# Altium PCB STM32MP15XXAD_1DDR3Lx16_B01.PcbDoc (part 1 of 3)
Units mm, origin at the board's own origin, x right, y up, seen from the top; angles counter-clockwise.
Board outline 86 x 120 mm, 4 copper layers (Top Layer, Signal Layer 1, Signal Layer 2, Bottom Layer), stack 1.571 mm thick; 118 components, 119 nets, 781 pads, 336 vias.
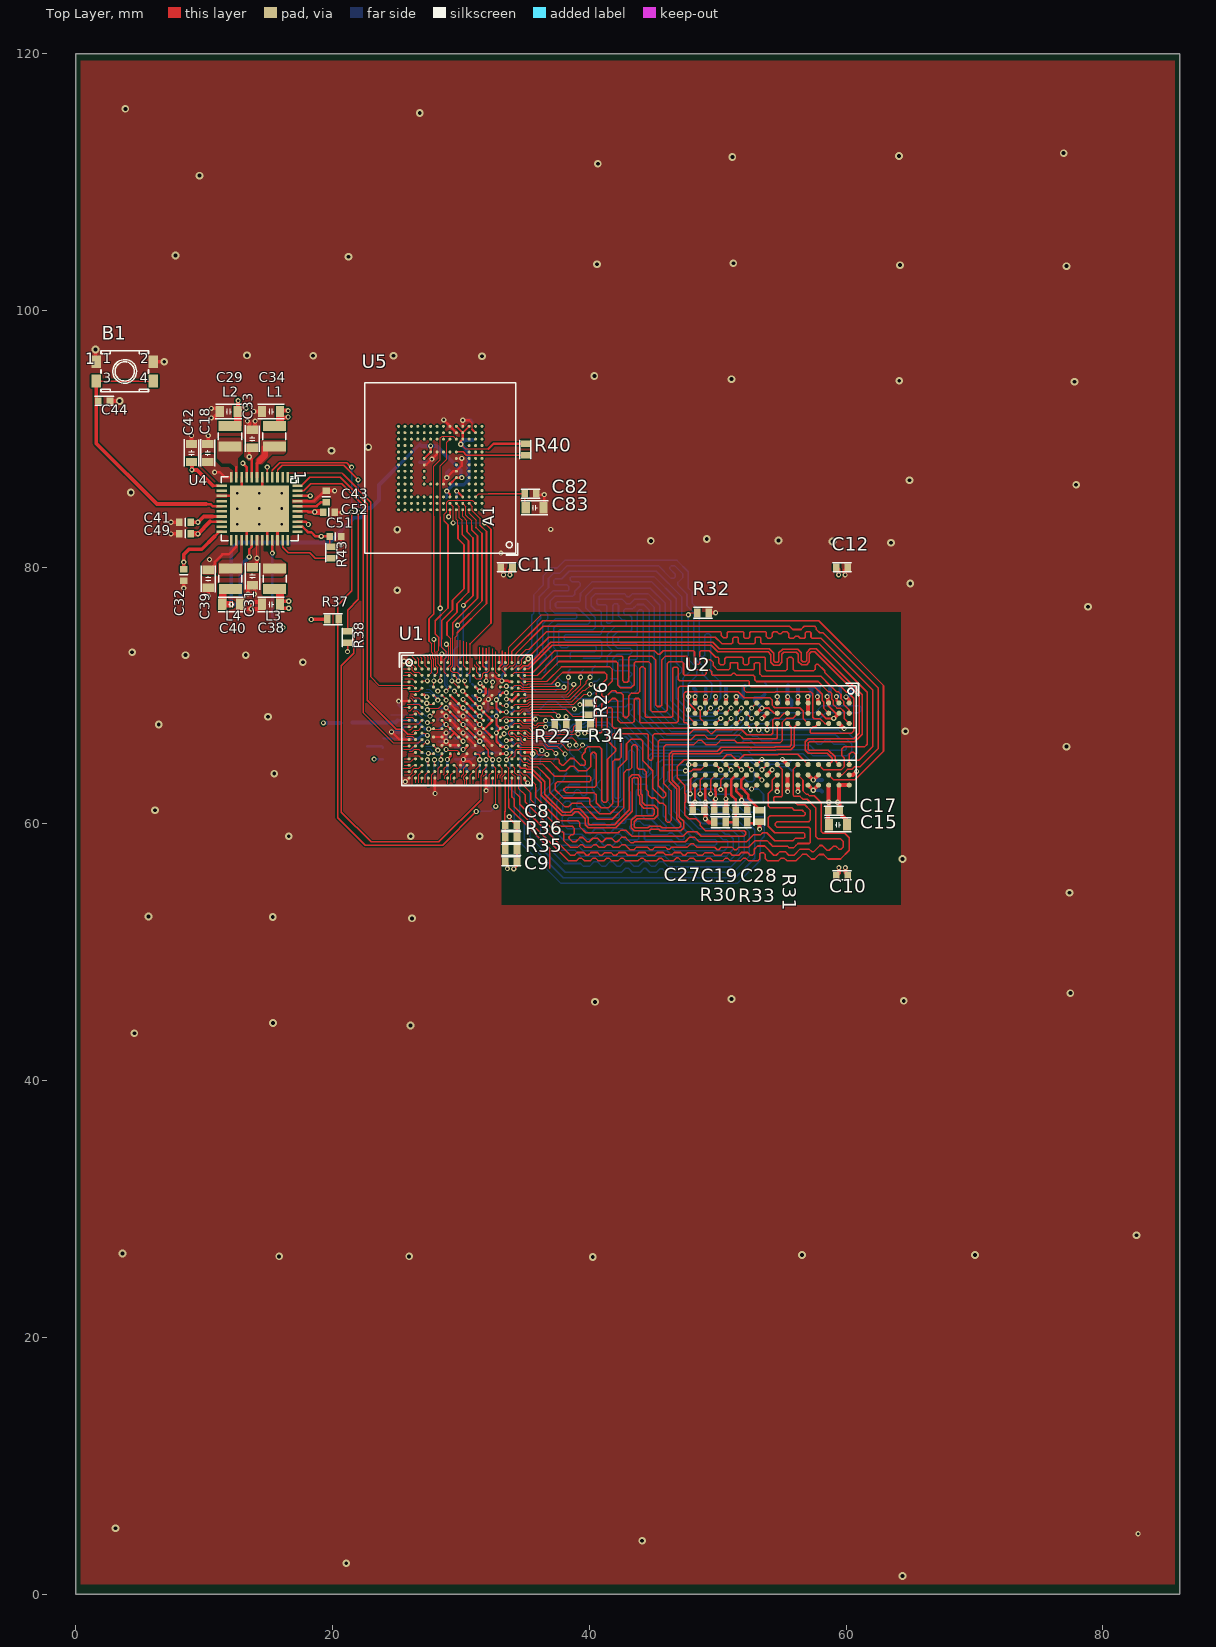
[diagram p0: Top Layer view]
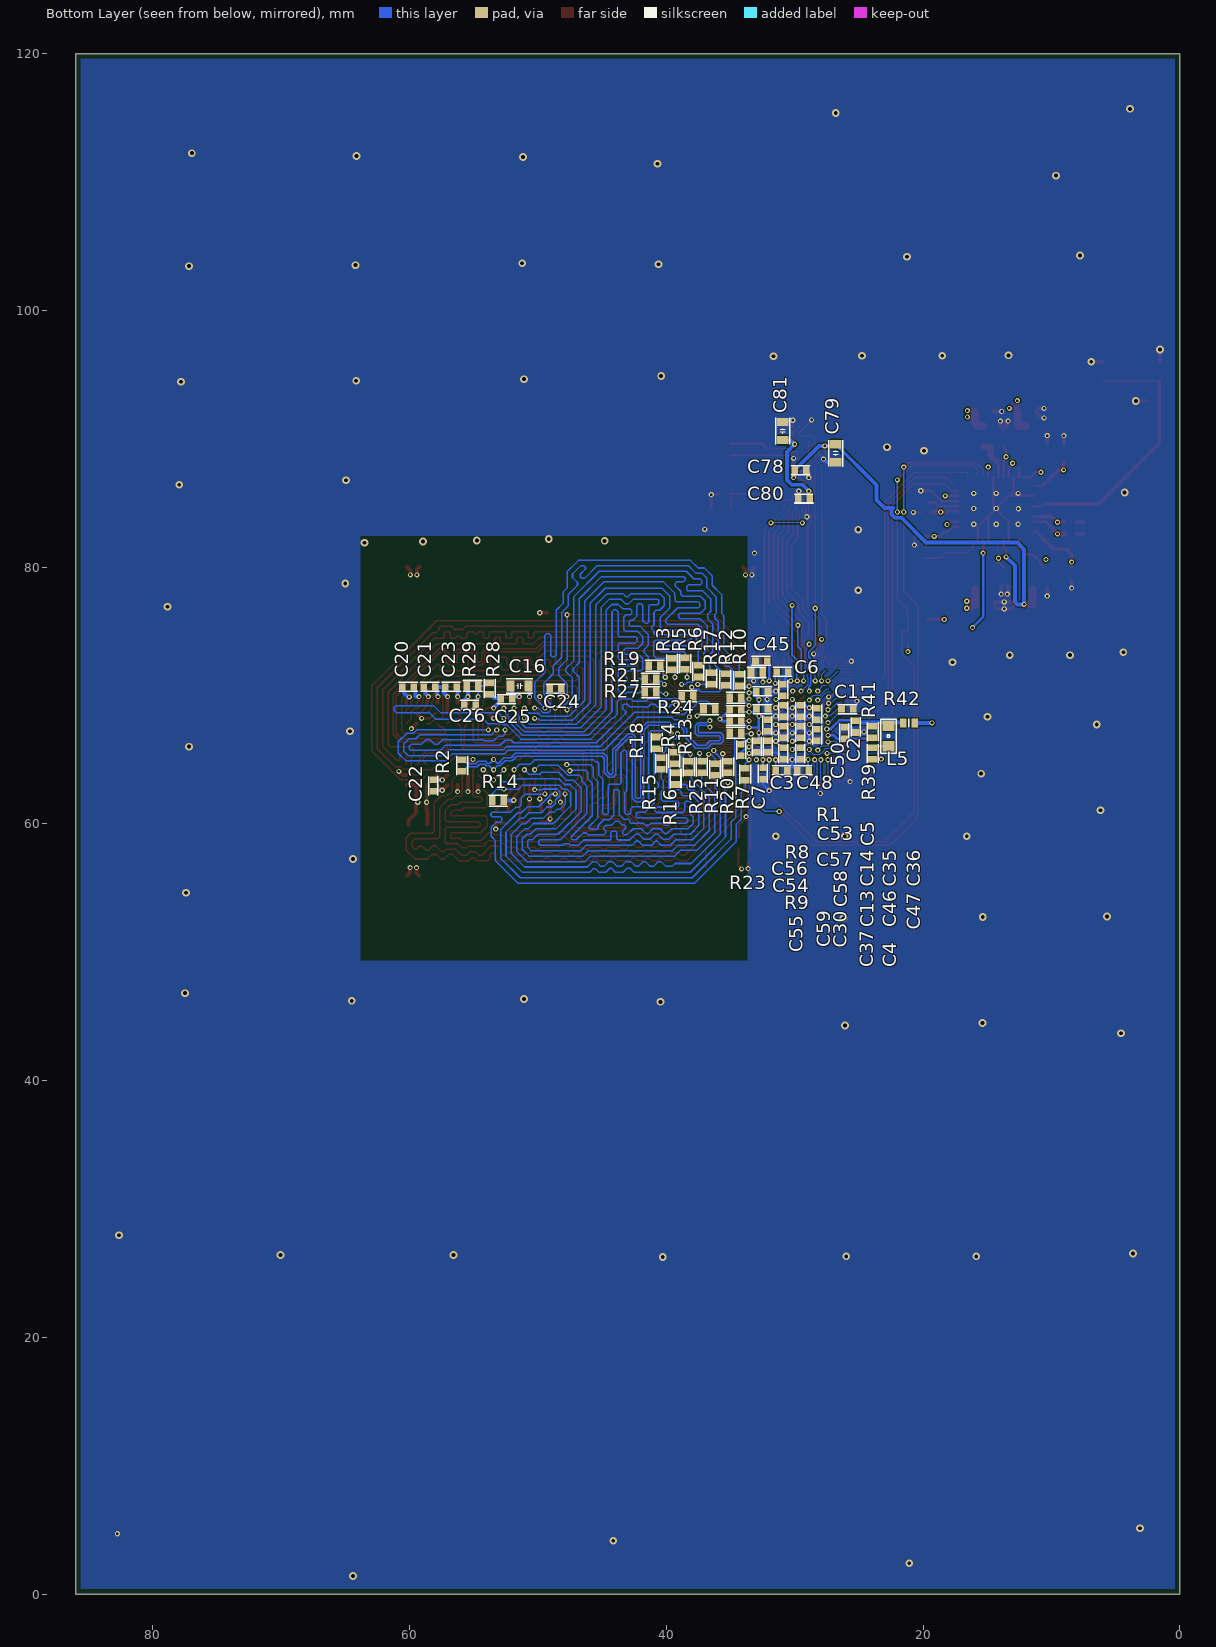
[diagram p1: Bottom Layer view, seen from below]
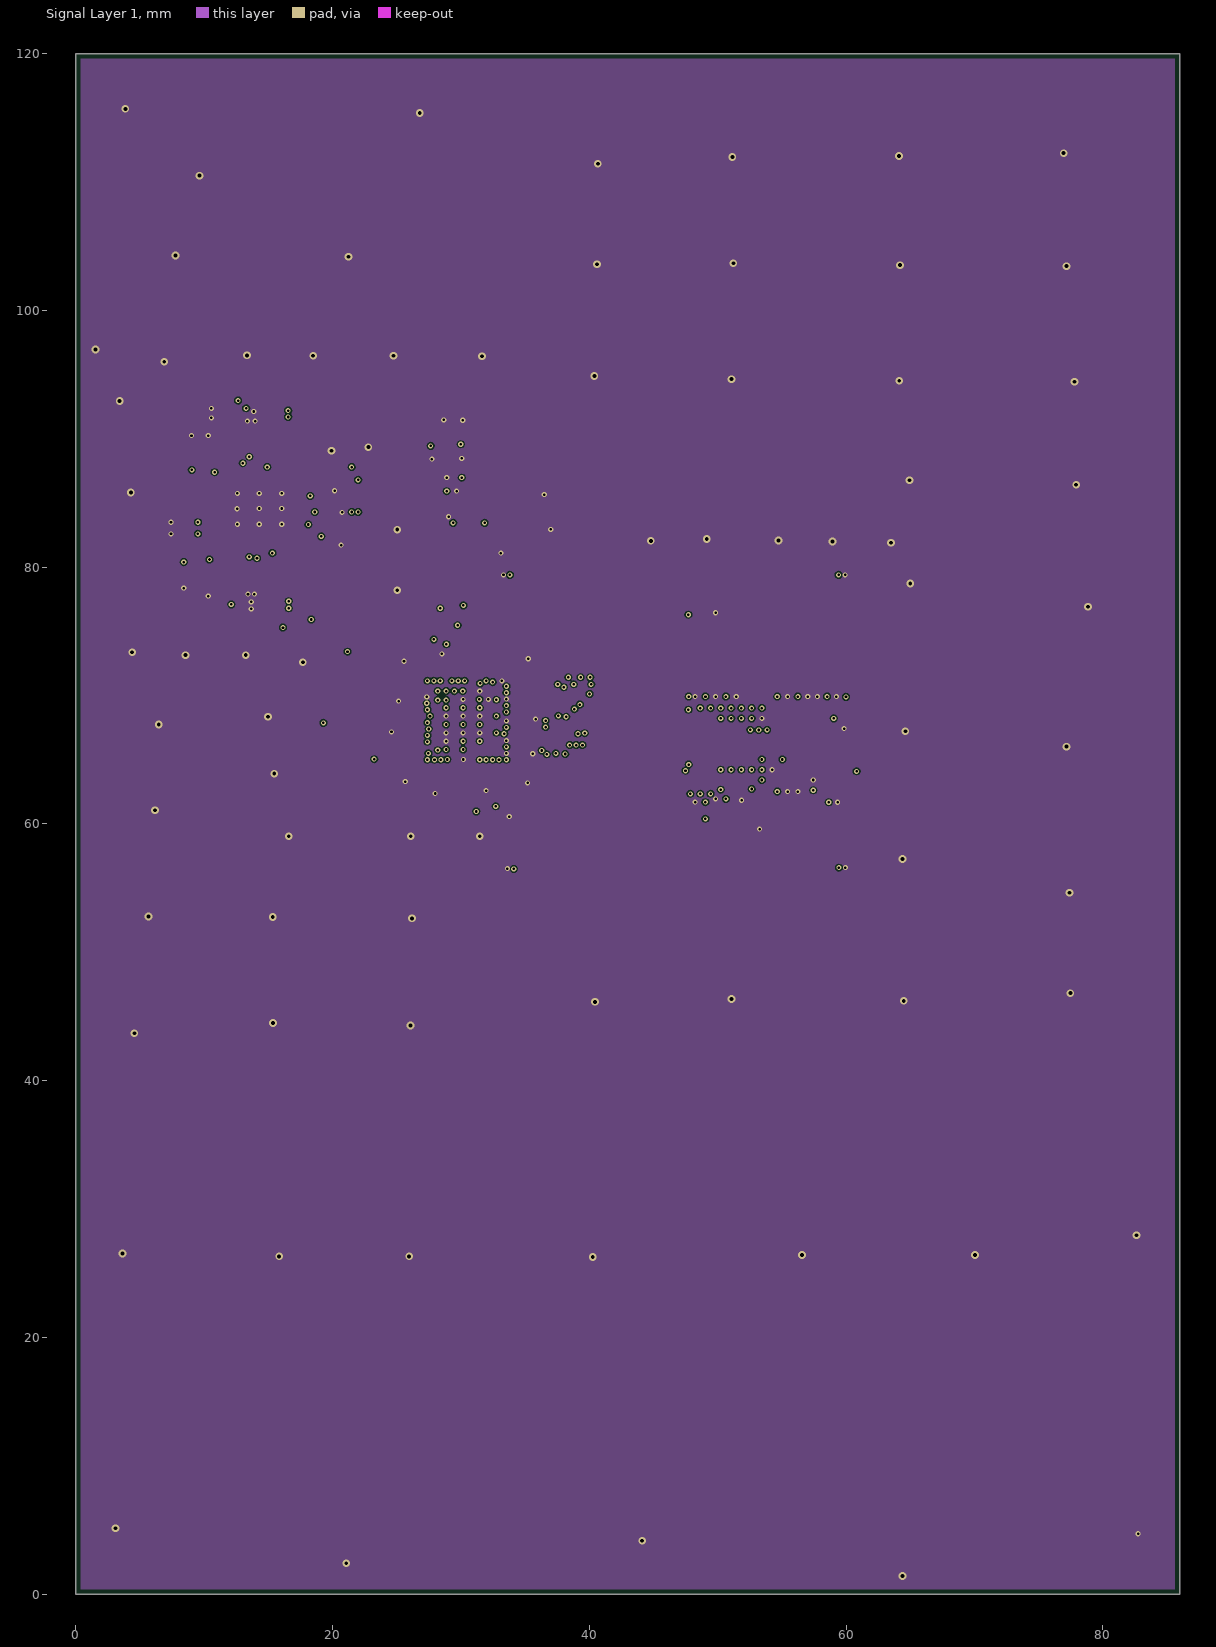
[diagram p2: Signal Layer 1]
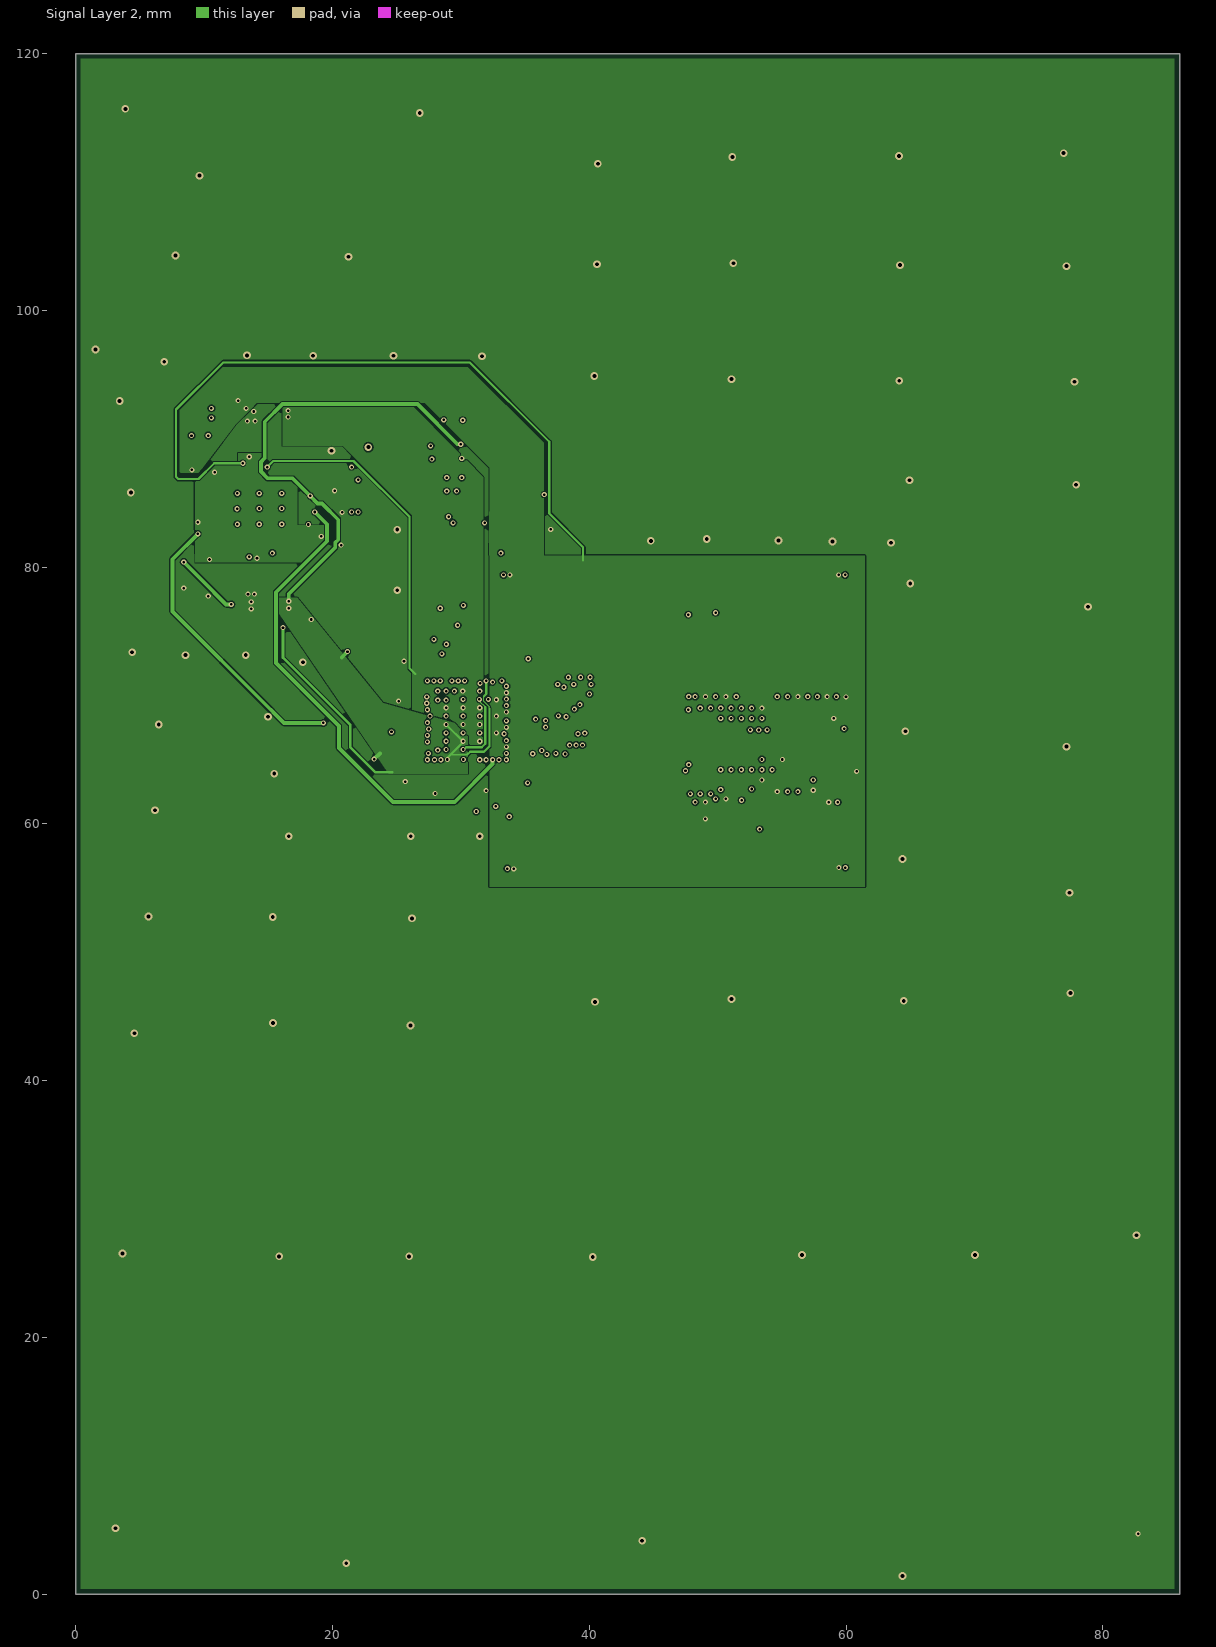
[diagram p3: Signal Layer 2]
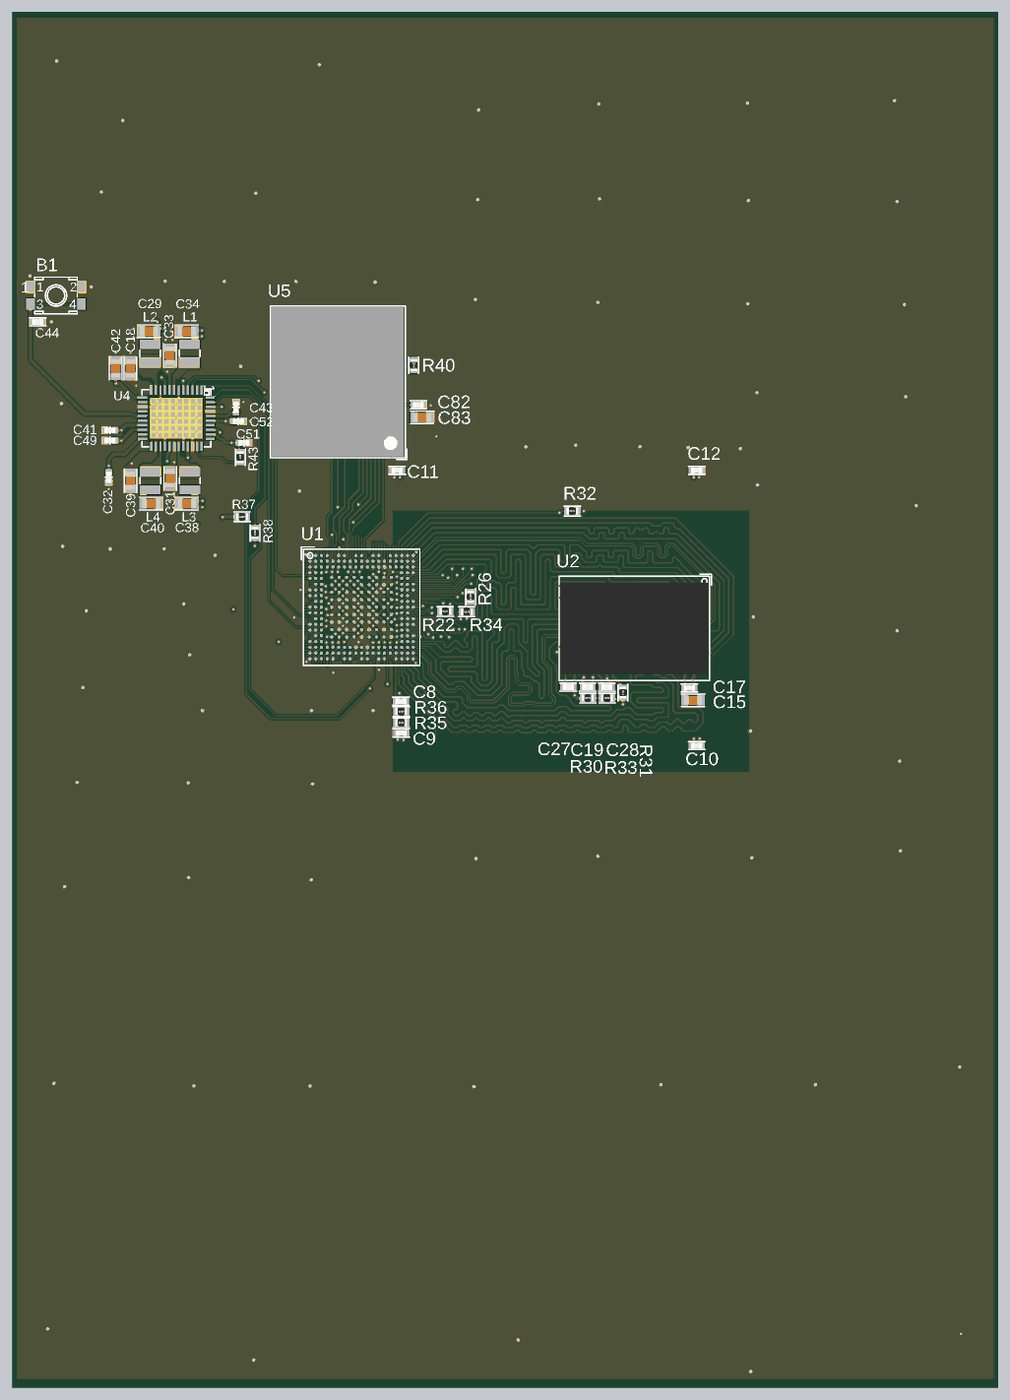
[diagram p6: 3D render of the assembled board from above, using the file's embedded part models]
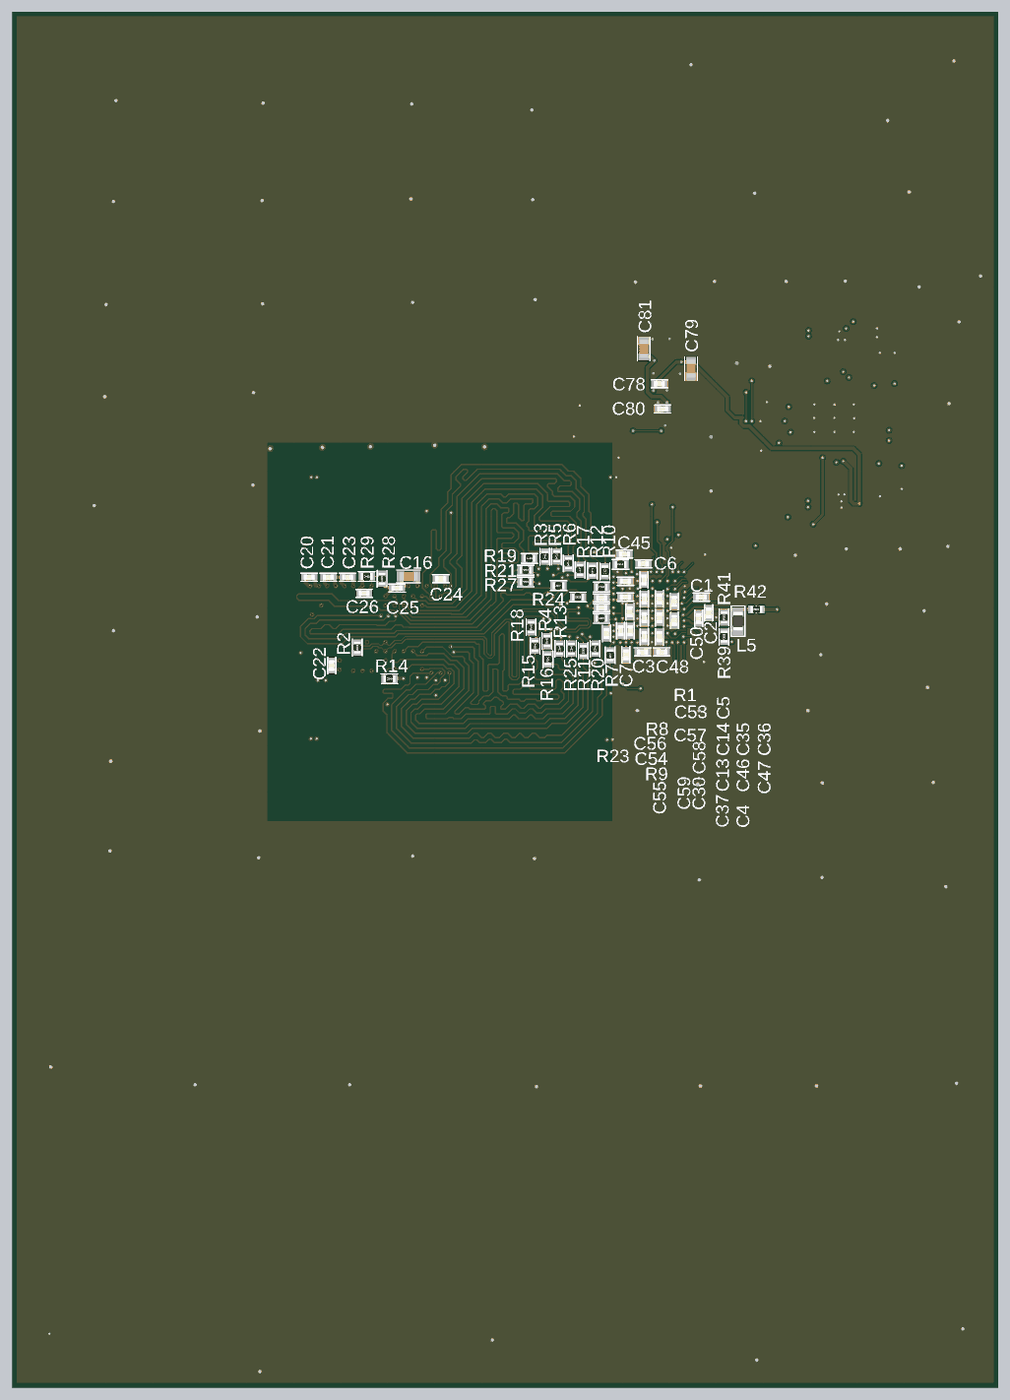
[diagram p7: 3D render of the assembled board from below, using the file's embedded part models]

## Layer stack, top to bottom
Top Solder: solder mask 0.0203, Solder Resist, Dk 3.5
Top Layer: signal copper 0.037
Dielectric 1: core 0.0986, FR-4, Dk 4.1
Signal Layer 1: signal copper 0.035
Dielectric 2: prepreg 1.23, Dk 4.25
Signal Layer 2: signal copper 0.035
Dielectric 3: core 0.0986, Dk 4.1
Bottom Layer: signal copper 0.037
Bottom Solder: solder mask 0.0203, Solder Resist, Dk 3.5

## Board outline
0,0 0,120 86,120 86,0

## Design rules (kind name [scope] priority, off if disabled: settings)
BoardOutlineClearance [All] p1: gap=0.4 ignorepadtopadclearanceinfootprint=FALSE
Clearance diff [InNetClass('diff')] p1: gap=0.1 ignorepadtopadclearanceinfootprint=FALSE except(0: Arc-Hole Track-Hole SMDPad-Hole THPad-Hole Via-Hole Fill-Hole Poly-Hole Region-Hole Text-Hole; 0.08: Track-SMDPad; 0.13: Track-Track; 0.15: Arc-Fill Track-Fill SMDPad-Fill THPad-Fill Via-Fill Fill-Fill; 0.2: Arc-THPad SMDPad-SMDPad SMDPad-THPad THPad-THPad)
Clearance [InNetClass('All Nets')] p2: gap=0.1 ignorepadtopadclearanceinfootprint=FALSE except(0: Arc-Hole Track-Hole SMDPad-Hole THPad-Hole Via-Hole Fill-Hole Poly-Hole Region-Hole Text-Hole; 0.08: Track-Track Track-SMDPad; 0.15: Arc-Fill Track-Fill SMDPad-Fill THPad-Fill Via-Fill Fill-Fill)
ComponentClearance [All] p1 off: gap=0.025 collisioncheckmode=3 verticalgap=2540 showdistances=TRUE
DiffPairsRouting [All] p1: maxlimit=0.13 minlimit=0.13 mostfreqgap=0.13 toplayer_minwidth=0.09 toplayer_maxwidth=0.1 toplayer_prefwidth=0.13 midlayer1_minwidth=0.09 midlayer1_maxwidth=0.1 midlayer1_prefwidth=0.13 midlayer2_minwidth=0.09 midlayer2_maxwidth=0.1 midlayer2_prefwidth=0.13 bottomlayer_minwidth=0.09 bottomlayer_maxwidth=0.1 bottomlayer_prefwidth=0.13 maxuncoupledlength=0.5
FanoutControl Fanout_BGA [IsBGA] p1: bgadir=Out bgaviamode=Closest fanoutstyle=Auto fanoutdirection=Alternating viagrid=0.025 // Fanout_BGA (Default Rule)
FanoutControl Fanout_LCC [IsLCC] p2: bgadir=Out bgaviamode=Closest fanoutstyle=Auto fanoutdirection=Alternating viagrid=0.025 // Fanout_LCC (Default Rule)
FanoutControl Fanout_SOIC [IsSOIC] p3: bgadir=Out bgaviamode=Closest fanoutstyle=Auto fanoutdirection=Alternating viagrid=0.025 // Fanout_SOIC (Default Rule)
FanoutControl Fanout_Small [(CompPinCount < 5)] p4: bgadir=Out bgaviamode=Closest fanoutstyle=Auto fanoutdirection=OutThenIn viagrid=0.025 // Fanout_Small (Default Rule)
FanoutControl Fanout_Default [All] p5: bgadir=Out bgaviamode=Closest fanoutstyle=Auto fanoutdirection=Alternating viagrid=0.025 // Fanout_Default (Default Rule)
Height [All] p1 off: minheight=0 maxheight=100 prefheight=0.5
HoleSize [All] p1: absolutevalues=TRUE maxlimit=10 minlimit=0.15 maxpercent=80.000 minpercent=20.000
HoleToHoleClearance [All] p1: gap=0.25 allowstackedmicrovias=TRUE
Length Length_SDMMC1 [InNetClass('NETC_SDMMC1')] p1: maxlimit=86 minlimit=81
MatchedLengths [All] p1: tolerance=25.4 checknetsindiffpair=FALSE checkdiffpairvsdiffpair=TRUE checkxsignals=TRUE checkothers=TRUE
MinimumSolderMaskSliver [All] p1: minsoldermaskwidth=0
PlaneClearance [All] p1: clearance=0.6
PlaneConnect [All] p1: planeconnectstyle=Direct reliefexpansion=0.508 reliefentries=4 reliefconductorwidth=0.254 reliefairgap=0.254
PolygonConnect [All] p1: connectstyle=Direct reliefconductorwidth=0.254 reliefentries=4 polygonreliefangle="90 Angle" airgapwidth=0.254
RoutingVias RoutingVias_GND [InNetClass('GND')] p1: holewidth=0.3 width=0.6 viastyle="Through Hole" minholewidth=0.2 minwidth=0.4 maxholewidth=0.3 maxwidth=0.6
RoutingVias RoutingVias_ALIMS [InNetClass('ALIMS')] p2: holewidth=0.3 width=0.6 viastyle="Through Hole" minholewidth=0.2 minwidth=0.4 maxholewidth=0.3 maxwidth=0.6
RoutingVias [All] p3: holewidth=0.2 width=0.4 viastyle="Through Hole" minholewidth=0.2 minwidth=0.4 maxholewidth=0.3 maxwidth=0.6
SilkToSilkClearance [All] p1: silktosilkclearance=0
SilkToSolderMaskClearance [IsPad] p1: minsilkscreentomaskgap=0 clearancetoexposedcopper=TRUE
SolderMaskExpansion [All] p1: expansion=0.05
Width VDD_DDR [InNet('VDD_DDR')] p1: maxlimit=0.3 minlimit=0.1 preferedwidth=0.175
Width Width_VCORE [InNet('VDD_CORE')] p2: maxlimit=0.2 minlimit=0.175 preferedwidth=0.175
Width Width_gnd [InNet('GND')] p3: maxlimit=0.3 minlimit=0.1 preferedwidth=0.175
Width [All] p4: maxlimit=0.3 minlimit=0.09 preferedwidth=0.09
15 further rules are at their usual default settings.

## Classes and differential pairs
differential pair class DIFF_CLK: DDR_CLK
differential pair class DIFF_DQS1: DDR_DQS1
differential pair class DIFF_DQS0: DDR_DQS0
polygon class POLY_DIRECT_ALL: NETC906_2_L01_P192
component class U_1DDR3L_16bits: C9 C10 C11 C12 C15 C16 C17 C19 C20 C21 C22 C23 C24 C25 C26 C27 C28 R2 R3 R4 R5 R6 R7 R8 R9 R10 R11 R12 R13 R14 R15 R16 R17 R18 R19 R20 R21 R22 R23 R24 R25 R26 R27 R28 R29 R30 R31 R32 R33 R34 U2
component class U_Power_MPU: C1 C2 C3 C4 C5 C6 C7 C13 C14 C30 C35 C36 C37 C45 C46 C47 C48 C50 C53 C54 C55 C56 C57 C58 C59 L5 R39 R41 R42
component class U_Power_PMIC: B1 C18 C29 C31 C32 C33 C34 C38 C39 C40 C41 C42 C43 C44 C49 C51 C52 L1 L2 L3 L4 R43 U4
component class U_eMMC: C78 C79 C80 C81 C82 C83 R40 U5
component class U_STM32_MPU_IOs: C8 R1 R35 R36 R37 R38 U1
net class eMMC_SDIO2_D[0..7]: eMMC_SDIO2_D0 eMMC_SDIO2_D1 eMMC_SDIO2_D2 eMMC_SDIO2_D3 eMMC_SDIO2_D4 eMMC_SDIO2_D5 eMMC_SDIO2_D6 eMMC_SDIO2_D7
differential pair DDR_CLK: +DDR_CLK_P -DDR_CLK_N
differential pair DDR_DQS0: +DDR_DQS0_P -DDR_DQS0_N
differential pair DDR_DQS1: +DDR_DQS1_P -DDR_DQS1_N

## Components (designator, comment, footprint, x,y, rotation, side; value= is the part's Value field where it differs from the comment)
B1 "" SWI_JIUBABA_C-TS-02H-2-5-B-V-T_R_BLUE 3.825,95.25 r0 top value=SW-PUSH-TS-02H-Blue
C1 "" C0402 25.9,68.95 r0 bottom value=100nF
C2 "" C0402 25.25,67.575 r90 bottom value=1uF
C3 "Capacitor" C0402 31.025,64.175 r0 bottom value=2.2uF
C4 "" C0402 29.55,65.5 r90 bottom value=100nF
C5 "Capacitor" C0402 30.9,70.45 r270 bottom value=2.2uF
C6 "Capacitor" C0402 30.95,71.85 r0 bottom value=2.2uF
C7 "" C0402 32.475,63.925 r90 bottom value=100nF
C8 "" C0402 33.9,59.875 r180 top value=100nF
C9 "" C0402 33.925,57.1 r0 top value=100nF
C10 "" C0402 59.7,56 r180 top value=100nF
C11 "" C0402 33.575,80 r0 top value=100nF
C12 "" C0402 59.7,80 r180 top value=100nF
C13 "" C0402 30.875,67.15 r90 bottom value=1uF
C14 "" C0402 30.875,68.8 r90 bottom value=1uF
C15 "" C0603 59.375,59.95 r180 top value=10uF
C16 "" C0603 51.425,70.75 r180 bottom value=10uF
C17 "" C0402 59.05,61.025 r180 top value=100nF
C18 "" C0603 10.3,88.9 r270 top value=10uF
C19 "" C0402 50.19,61.1 r0 top value=100nF
C20 "" C0402 60.1,70.675 r0 bottom value=100nF
C21 "" C0402 58.425,70.675 r0 bottom value=100nF
C22 "" C0402 58.13,62.985 r90 bottom value=100nF
C23 "" C0402 56.75,70.675 r180 bottom value=100nF
C24 "" C0402 48.625,70.55 r0 bottom value=100nF
C25 "" C0402 52.45,69.725 r0 bottom value=100nF
C26 "" C0402 55.3,69.275 r180 bottom value=100nF
C27 "" C0402 48.5,61.1 r0 top value=100nF
C28 "" C0402 51.86,61.1 r180 top value=100nF
C29 "" C0603 11.925,92.125 r0 top value=22uF
C30 "" C0402 32.1,66.025 r90 bottom value=1uF
C31 "" C0603 13.775,79.3 r90 top value=10uF
C32 "" C0402 8.425,79.4 r90 top value=1uF
C33 "" C0603 13.75,90 r270 top value=10uF
C34 "" C0603 15.225,92.125 r0 top value=22uF
C35 "" C0402 29.55,68.8 r90 bottom value=1uF
C36 "" C0402 28.25,68.575 r90 bottom value=1uF
C37 "" C0402 30.875,65.5 r90 bottom value=1uF
C38 "" C0603 15.225,77.1 r0 top value=22uF
C39 "" C0603 10.325,79.1 r90 top value=10uF
C40 "" C0603 12.125,77.1 r180 top value=22uF
C41 "" C0402 8.525,83.5 r0 top value=1uF
C42 "" C0603 9.025,88.9 r270 top value=10uF
C43 "" C0402 19.525,85.5 r270 top value=4.7uF
C44 "" C0402 2.225,92.95 r180 top value=10nF
C45 "" C0402 32.6,72.7 r180 bottom value=1uF
C46 "" C0402 29.55,67.15 r270 bottom value=1uF
C47 "" C0402 28.25,66.925 r90 bottom value=1uF
C48 "" C0402 29.35,64.175 r180 bottom value=1uF
C49 "" C0402 8.525,82.6 r0 top value=4.7uF
C50 "" C0402 26.125,67.1 r270 bottom value=1uF
C51 "" C0402 20.225,82.4 r0 top value=4.7uF
C52 "" C0402 19.725,84.275 r180 top value=4.7uF
C53 "" C0402 32.525,70.325 r0 bottom value=1uF
C54 "" C0402 34.6,68.025 r180 bottom value=1uF
C55 "Capacitor" C0402 34.175,65.775 r270 bottom value=3.3nF
C56 "Capacitor" C0402 34.6,68.875 r180 bottom value=3.3nF
C57 "Capacitor" C0402 32.525,68.95 r0 bottom value=3.3nF
C58 "" C0402 32.125,67.675 r90 bottom value=1nF
C59 "" C0402 32.95,66.025 r90 bottom value=1nF
C78 "" C0402 29.55,87.55 r0 bottom value=100nF
C79 "" C0603 26.8,88.875 r90 bottom value=2.2uF
C80 "" C0402 29.275,85.35 r180 bottom value=100nF
C81 "" C0603 30.925,90.6 r270 bottom value=2.2uF
C82 "" C0402 35.425,85.725 r180 top value=100nF
C83 "" C0603 35.75,84.625 r180 top value=2.2uF
L1 "" IND_MURATA_DFE201612P 15.475,90.2 r90 top value=DFE201612P-1R0M
L2 "" IND_MURATA_DFE201612P 12.025,90.2 r90 top value=DFE201612P-1R0M
L3 "" IND_MURATA_DFE201612P 15.5,79.1 r270 top value=DFE201612P-1R0M
L4 "" IND_MURATA_DFE201612P 12.05,79.1 r270 top value=DFE201612P-1R0M
L5 "" L0603_H0P8 22.7,66.85 r90 bottom value=LQM18FN4R7M00D
R1 "" R0402 32.95,71.8 r180 bottom value=240R
R2 "" R0402 55.9,64.55 r270 bottom value=100R
R3 "" R0402 39.55,72.475 r90 bottom value=33R
R4 "" R0402 39.375,65.125 r270 bottom value=33R
R5 "" R0402 38.525,72.5 r90 bottom value=33R
R6 "" R0402 37.5,71.9 r90 bottom value=33R
R7 "" R0402 33.85,63.875 r270 bottom value=33R
R8 "" R0402 34.6,69.825 r0 bottom value=33R
R9 "" R0402 34.6,67.1 r0 bottom value=33R
R10 "" R0402 34.3,71.2 r90 bottom value=33R
R11 "" R0402 36.2,64.25 r270 bottom value=33R
R12 "" R0402 35.4,71.25 r90 bottom value=33R
R13 "" R0402 38.25,64.45 r270 bottom value=33R
R14 "" R0402 53.1,61.825 r0 bottom value=10K
R15 "" R0402 40.4,64.7 r270 bottom value=33R
R16 "" R0402 39.275,63.525 r270 bottom value=33R
R17 "" R0402 36.475,71.325 r90 bottom value=33R
R18 "" R0402 40.75,66.325 r270 bottom value=33R
R19 "" R0402 40.9,72.325 r0 bottom value=33R
R20 "" R0402 35.175,64.45 r270 bottom value=33R
R21 "" R0402 41.225,71.3 r0 bottom value=33R
R22 "" R0402 37.775,67.7 r0 top value=33R
R23 "" R0402 36.65,68.95 r180 bottom value=33R
R24 "" R0402 38.35,69.95 r0 bottom value=33R
R25 "" R0402 37.225,64.45 r270 bottom value=33R
R26 "" R0402 39.975,68.975 r90 top value=33R
R27 "" R0402 41.225,70.275 r0 bottom value=33R
R28 "" R0402 53.75,70.55 r270 bottom value=1K
R29 "" R0402 55.075,70.75 r180 bottom value=1K
R30 "" R0402 50.2,60.15 r180 top value=1K
R31 "" R0402 53.26,60.625 r90 top value=240R
R32 "" R0402 48.85,76.45 r180 top value=10K
R33 "" R0402 51.875,60.15 r180 top value=1K
R34 "" R0402 39.65,67.675 r0 top value=33R
R35 "" R0402 33.925,58 r0 top value=1K
R36 "" R0402 33.925,58.975 r180 top value=1K
R37 "" R0402 20.05,75.95 r0 top value=1K5
R38 "" R0402 21.175,74.55 r90 top value=1K5
R39 "" R0402 23.925,65.5 r90 bottom value=0R
R40 "" R0402 35.025,89.175 r90 top value=10K
R41 "" R0402 23.925,67.175 r270 bottom value=0R
R42 "" R0402 21.1,67.875 r0 bottom value=0R
R43 "" R0402 19.9,81.15 r90 top value=47K
U1 "" ICC_TFBGA257_10X10_STM32MP157CAD3_P050-065 30.475,68.075 r0 top value=STM32MP157CAD3
U2 "NT5CC256M16ER-EK" ICC_VFBGA96_9X13_P080 54.25,66.225 r270 top locked
U4 "" ICC_WFQFN44-EPAD_5X6_P040 14.325,84.55 r270 top value=STPMIC1APQR
U5 "" ICC_P-WFBGA153_13X11P5_P050 28.4,87.725 r90 top locked value=THGBMDG5D1LBAIL

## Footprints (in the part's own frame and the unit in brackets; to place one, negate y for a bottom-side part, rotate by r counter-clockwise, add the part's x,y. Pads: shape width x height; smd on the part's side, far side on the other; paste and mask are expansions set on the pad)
C0402 [mm]
  rect 0.51x0.56 smd mask+0.05: 1(-0.45,0) 2(0.45,0)
  silkscreen extent -0.72,-0.35 0.72,0.35, body extent -0.5,-0.3 0.5,0.3, height 0.4
C0603 [mm]
  rect 0.64x0.89 smd mask+0.05: 1(-0.7,0) 2(0.7,0)
  silkscreen extent -1.05,-0.55 1.02,0.55, body extent -0.9,-0.5 0.9,0.5, height 1.4
ICC_P-WFBGA153_13X11P5_P050 [mm]
  round 0.23 smd mask+0.05: A1(-3.25,-3.25) A2(-3.25,-2.75) A3(-3.25,-2.25) A4(-3.25,-1.75) A5(-3.25,-1.25) A6(-3.25,-0.75) A7(-3.25,-0.25) A8(-3.25,0.25) A9(-3.25,0.75) A10(-3.25,1.25) A11(-3.25,1.75) A12(-3.25,2.25) A13(-3.25,2.75) A14(-3.25,3.25) B1(-2.75,-3.25) B2(-2.75,-2.75) B3(-2.75,-2.25) B4(-2.75,-1.75) B5(-2.75,-1.25) B6(-2.75,-0.75) B7(-2.75,-0.25) B8(-2.75,0.25) B9(-2.75,0.75) B10(-2.75,1.25) B11(-2.75,1.75) B12(-2.75,2.25) B13(-2.75,2.75) B14(-2.75,3.25) C1(-2.25,-3.25) C2(-2.25,-2.75) C3(-2.25,-2.25) C4(-2.25,-1.75) C5(-2.25,-1.25) C6(-2.25,-0.75) C7(-2.25,-0.25) C8(-2.25,0.25) C9(-2.25,0.75) C10(-2.25,1.25) C11(-2.25,1.75) C12(-2.25,2.25) C13(-2.25,2.75) C14(-2.25,3.25) D1(-1.75,-3.25) D2(-1.75,-2.75) D3(-1.75,-2.25) D4(-1.75,-1.75) D12(-1.75,2.25) D13(-1.75,2.75) D14(-1.75,3.25) E1(-1.25,-3.25) E2(-1.25,-2.75) E3(-1.25,-2.25) E5(-1.25,-1.25) E6(-1.25,-0.75) E7(-1.25,-0.25) E8(-1.25,0.25) E9(-1.25,0.75) E10(-1.25,1.25) E12(-1.25,2.25) E13(-1.25,2.75) E14(-1.25,3.25) F1(-0.75,-3.25) F2(-0.75,-2.75) F3(-0.75,-2.25) F5(-0.75,-1.25) F10(-0.75,1.25) F12(-0.75,2.25) F13(-0.75,2.75) F14(-0.75,3.25) G1(-0.25,-3.25) G2(-0.25,-2.75) G3(-0.25,-2.25) G5(-0.25,-1.25) G10(-0.25,1.25) G12(-0.25,2.25) G13(-0.25,2.75) G14(-0.25,3.25) H1(0.25,-3.25) H2(0.25,-2.75) H3(0.25,-2.25) H5(0.25,-1.25) H10(0.25,1.25) H12(0.25,2.25) H13(0.25,2.75) H14(0.25,3.25) J1(0.75,-3.25) J2(0.75,-2.75) J3(0.75,-2.25) J5(0.75,-1.25) J10(0.75,1.25) J12(0.75,2.25) J13(0.75,2.75) J14(0.75,3.25) K1(1.25,-3.25) K2(1.25,-2.75) K3(1.25,-2.25) K5(1.25,-1.25) K6(1.25,-0.75) K7(1.25,-0.25) K8(1.25,0.25) K9(1.25,0.75) K10(1.25,1.25) K12(1.25,2.25) K13(1.25,2.75) K14(1.25,3.25) L1(1.75,-3.25) L2(1.75,-2.75) L3(1.75,-2.25) L12(1.75,2.25) L13(1.75,2.75) L14(1.75,3.25) M1(2.25,-3.25) M2(2.25,-2.75) M3(2.25,-2.25) M4(2.25,-1.75) M5(2.25,-1.25) M6(2.25,-0.75) M7(2.25,-0.25) M8(2.25,0.25) M9(2.25,0.75) M10(2.25,1.25) M11(2.25,1.75) M12(2.25,2.25) M13(2.25,2.75) M14(2.25,3.25) N1(2.75,-3.25) N2(2.75,-2.75) N3(2.75,-2.25) N4(2.75,-1.75) N5(2.75,-1.25) N6(2.75,-0.75) N7(2.75,-0.25) N8(2.75,0.25) N9(2.75,0.75) N10(2.75,1.25) N11(2.75,1.75) N12(2.75,2.25) N13(2.75,2.75) N14(2.75,3.25) P1(3.25,-3.25) P2(3.25,-2.75) P3(3.25,-2.25) P4(3.25,-1.75) P5(3.25,-1.25) P6(3.25,-0.75) P7(3.25,-0.25) P8(3.25,0.25) P9(3.25,0.75) P10(3.25,1.25) P11(3.25,1.75) P12(3.25,2.25) P13(3.25,2.75) P14(3.25,3.25)
  silkscreen extent -6.78,-6.02 6.63,5.87, body extent -6.55,-5.8 6.55,5.8, height 1
ICC_TFBGA257_10X10_STM32MP157CAD3_P050-065 [mm] "MCD-01144"
  round 0.23 smd paste+0.025 mask+0.05: 1A1(-2.6,2.6) 1A2(-1.95,2.6) 1A3(-1.3,2.6) 1A4(-0.65,2.6) 1A5(0,2.6) 1A6(0.65,2.6) 1A7(1.3,2.6) 1A8(1.95,2.6) 1A9(2.6,2.6) 1B1(-2.6,1.95) 1B2(-1.95,1.95) 1B3(-1.3,1.95) 1B4(-0.65,1.95) 1B5(0,1.95) 1B6(0.65,1.95) 1B7(1.3,1.95) 1B8(1.95,1.95) 1B9(2.6,1.95) 1C1(-2.6,1.3) 1C2(-1.95,1.3) 1C3(-1.3,1.3) 1C4(-0.65,1.3) 1C5(0,1.3) 1C6(0.65,1.3) 1C7(1.3,1.3) 1C8(1.95,1.3) 1C9(2.6,1.3) 1D1(-2.6,0.65) 1D2(-1.95,0.65) 1D3(-1.3,0.65) 1D4(-0.65,0.65) 1D5(0,0.65) 1D6(0.65,0.65) 1D7(1.3,0.65) 1D8(1.95,0.65) 1D9(2.6,0.65) 1E1(-2.6,0) 1E2(-1.95,0) 1E3(-1.3,0) 1E4(-0.65,0) 1E5(0,0) 1E6(0.65,0) 1E7(1.3,0) 1E8(1.95,0) 1E9(2.6,0) 1F1(-2.6,-0.65) 1F2(-1.95,-0.65) 1F3(-1.3,-0.65) 1F4(-0.65,-0.65) 1F5(0,-0.65) 1F6(0.65,-0.65) 1F7(1.3,-0.65) 1F8(1.95,-0.65) 1F9(2.6,-0.65) 1G1(-2.6,-1.3) 1G2(-1.95,-1.3) 1G3(-1.3,-1.3) 1G4(-0.65,-1.3) 1G5(0,-1.3) 1G6(0.65,-1.3) 1G7(1.3,-1.3) 1G8(1.95,-1.3) 1G9(2.6,-1.3) 1H1(-2.6,-1.95) 1H2(-1.95,-1.95) 1H3(-1.3,-1.95) 1H4(-0.65,-1.95) 1H5(0,-1.95) 1H6(0.65,-1.95) 1H7(1.3,-1.95) 1H8(1.95,-1.95) 1H9(2.6,-1.95) 1J1(-2.6,-2.6) 1J2(-1.95,-2.6) 1J3(-1.3,-2.6) 1J4(-0.65,-2.6) 1J5(0,-2.6) 1J6(0.65,-2.6) 1J7(1.3,-2.6) 1J8(1.95,-2.6) 1J9(2.6,-2.6) A1(-4.5,4.5) A2(-4,4.5) A3(-3.5,4.5) A4(-3,4.5) A6(-2,4.5) A7(-1.5,4.5) A9(-0.5,4.5) A10(0,4.5) A12(1,4.5) A13(1.5,4.5) A15(2.5,4.5) A16(3,4.5) A17(3.5,4.5) A18(4,4.5) A19(4.5,4.5) B1(-4.5,4) B2(-4,4) B3(-3.5,4) B4(-3,4) B5(-2.5,4) B6(-2,4) B7(-1.5,4) B8(-1,4) B9(-0.5,4) B10(0,4) B11(0.5,4) B12(1,4) B13(1.5,4) B14(2,4) B15(2.5,4) B16(3,4) B17(3.5,4) B18(4,4) B19(4.5,4) C1(-4.5,3.5) C2(-4,3.5) C3(-3.5,3.5) C4(-3,3.5) C5(-2.5,3.5) C6(-2,3.5) C7(-1.5,3.5) C8(-1,3.5) C9(-0.5,3.5) C10(0,3.5) C11(0.5,3.5) C12(1,3.5) C13(1.5,3.5) C14(2,3.5) C15(2.5,3.5) C16(3,3.5) C17(3.5,3.5) C18(4,3.5) C19(4.5,3.5) D1(-4.5,3) D2(-4,3) D3(-3.5,3) D17(3.5,3) D18(4,3) D19(4.5,3) E1(-4.5,2.5) E2(-4,2.5) E3(-3.5,2.5) E17(3.5,2.5) E18(4,2.5) F2(-4,2) F3(-3.5,2) F17(3.5,2) F18(4,2) F19(4.5,2) G1(-4.5,1.5) G2(-4,1.5) G3(-3.5,1.5) G17(3.5,1.5) G18(4,1.5) G19(4.5,1.5) H1(-4.5,1) H2(-4,1) H3(-3.5,1) H17(3.5,1) H18(4,1) J2(-4,0.5) J3(-3.5,0.5) J17(3.5,0.5) J18(4,0.5) J19(4.5,0.5) K1(-4.5,0) K2(-4,0) K3(-3.5,0) K17(3.5,0) K18(4,0) K19(4.5,0) L1(-4.5,-0.5) L2(-4,-0.5) L3(-3.5,-0.5) L17(3.5,-0.5) L18(4,-0.5) M2(-4,-1) M3(-3.5,-1) M17(3.5,-1) M18(4,-1) M19(4.5,-1) N1(-4.5,-1.5) N2(-4,-1.5) N3(-3.5,-1.5) N17(3.5,-1.5) N18(4,-1.5) N19(4.5,-1.5) P1(-4.5,-2) P2(-4,-2) P3(-3.5,-2) P17(3.5,-2) P18(4,-2) R2(-4,-2.5) R3(-3.5,-2.5) R17(3.5,-2.5) R18(4,-2.5) R19(4.5,-2.5) T1(-4.5,-3) T2(-4,-3) T3(-3.5,-3) T17(3.5,-3) T18(4,-3) T19(4.5,-3) U1(-4.5,-3.5) U2(-4,-3.5) U3(-3.5,-3.5) U4(-3,-3.5) U5(-2.5,-3.5) U6(-2,-3.5) U7(-1.5,-3.5) U8(-1,-3.5) U9(-0.5,-3.5) U10(0,-3.5) U11(0.5,-3.5) U12(1,-3.5) U13(1.5,-3.5) U14(2,-3.5) U15(2.5,-3.5) U16(3,-3.5) U17(3.5,-3.5) U18(4,-3.5) U19(4.5,-3.5) V1(-4.5,-4) V2(-4,-4) V3(-3.5,-4) V4(-3,-4) V5(-2.5,-4) V6(-2,-4) V7(-1.5,-4) V8(-1,-4) V9(-0.5,-4) V10(0,-4) V11(0.5,-4) V12(1,-4) V13(1.5,-4) V14(2,-4) V15(2.5,-4) V16(3,-4) V17(3.5,-4) V18(4,-4) V19(4.5,-4) W1(-4.5,-4.5) W2(-4,-4.5) W3(-3.5,-4.5) W4(-3,-4.5) W5(-2.5,-4.5) W7(-1.5,-4.5) W8(-1,-4.5) W10(0,-4.5) W11(0.5,-4.5) W13(1.5,-4.5) W14(2,-4.5) W16(3,-4.5) W17(3.5,-4.5) W18(4,-4.5) W19(4.5,-4.5)
  silkscreen extent -5.25,-5.07 5.07,5.25, body extent -5.07,-5.07 5.07,5.07, height 1.21
ICC_VFBGA96_9X13_P080 [mm]
  round 0.4 smd mask+0.05: A1(-3.2,6) A2(-2.4,6) A3(-1.6,6) A7(1.6,6) A8(2.4,6) A9(3.2,6) B1(-3.2,5.2) B2(-2.4,5.2) B3(-1.6,5.2) B7(1.6,5.2) B8(2.4,5.2) B9(3.2,5.2) C1(-3.2,4.4) C2(-2.4,4.4) C3(-1.6,4.4) C7(1.6,4.4) C8(2.4,4.4) C9(3.2,4.4) D1(-3.2,3.6) D2(-2.4,3.6) D3(-1.6,3.6) D7(1.6,3.6) D8(2.4,3.6) D9(3.2,3.6) E1(-3.2,2.8) E2(-2.4,2.8) E3(-1.6,2.8) E7(1.6,2.8) E8(2.4,2.8) E9(3.2,2.8) F1(-3.2,2) F2(-2.4,2) F3(-1.6,2) F7(1.6,2) F8(2.4,2) F9(3.2,2) G1(-3.2,1.2) G2(-2.4,1.2) G3(-1.6,1.2) G7(1.6,1.2) G8(2.4,1.2) G9(3.2,1.2) H1(-3.2,0.4) H2(-2.4,0.4) H3(-1.6,0.4) H7(1.6,0.4) H8(2.4,0.4) H9(3.2,0.4) J1(-3.2,-0.4) J2(-2.4,-0.4) J3(-1.6,-0.4) J7(1.6,-0.4) J8(2.4,-0.4) J9(3.2,-0.4) K1(-3.2,-1.2) K2(-2.4,-1.2) K3(-1.6,-1.2) K7(1.6,-1.2) K8(2.4,-1.2) K9(3.2,-1.2) L1(-3.2,-2) L2(-2.4,-2) L3(-1.6,-2) L7(1.6,-2) L8(2.4,-2) L9(3.2,-2) M1(-3.2,-2.8) M2(-2.4,-2.8) M3(-1.6,-2.8) M7(1.6,-2.8) M8(2.4,-2.8) M9(3.2,-2.8) N1(-3.2,-3.6) N2(-2.4,-3.6) N3(-1.6,-3.6) N7(1.6,-3.6) N8(2.4,-3.6) N9(3.2,-3.6) P1(-3.2,-4.4) P2(-2.4,-4.4) P3(-1.6,-4.4) P7(1.6,-4.4) P8(2.4,-4.4) P9(3.2,-4.4) R1(-3.2,-5.2) R2(-2.4,-5.2) R3(-1.6,-5.2) R7(1.6,-5.2) R8(2.4,-5.2) R9(3.2,-5.2) T1(-3.2,-6) T2(-2.4,-6) T3(-1.6,-6) T7(1.6,-6) T8(2.4,-6) T9(3.2,-6)
  silkscreen extent -4.72,-6.55 4.55,6.73, body extent -4.55,-6.55 4.55,6.55, height 1
ICC_WFQFN44-EPAD_5X6_P040 [mm]
  rect 0.8x0.2 smd mask+0.05: 1(-2.45,2.2) 2(-2.45,1.8) 3(-2.45,1.4) 4(-2.45,1) 5(-2.45,0.6) 6(-2.45,0.2) 7(-2.45,-0.2) 8(-2.45,-0.6) 9(-2.45,-1) 10(-2.45,-1.4) 11(-2.45,-1.8) 12(-2.45,-2.2) 23(2.45,-2.2) 24(2.45,-1.8) 25(2.45,-1.4) 26(2.45,-1) 27(2.45,-0.6) 28(2.45,-0.2) 29(2.45,0.2) 30(2.45,0.6) 31(2.45,1) 32(2.45,1.4) 33(2.45,1.8) 34(2.45,2.2)
  rect 0.2x0.8 smd mask+0.05: 13(-1.8,-2.95) 14(-1.4,-2.95) 15(-1,-2.95) 16(-0.6,-2.95) 17(-0.2,-2.95) 18(0.2,-2.95) 19(0.6,-2.95) 20(1,-2.95) 21(1.4,-2.95) 22(1.8,-2.95) 35(1.8,2.95) 36(1.4,2.95) 37(1,2.95) 38(0.6,2.95) 39(0.2,2.95) 40(-0.2,2.95) 41(-0.6,2.95) 42(-1,2.95) 43(-1.4,2.95) 44(-1.8,2.95)
  rect 3.6x4.6 smd paste-1.8 mask+0.05: ep(0,0)
  silkscreen extent -2.5,-3 2.5,3, body extent -2.5,-3 2.5,3, height 0.81
IND_MURATA_DFE201612P [mm] "MCD-01491"
  rect 0.8x1.8 smd mask+0.05: 1(-0.8,0) 2(0.8,0)
  silkscreen extent -0.28,-0.9 0.28,0.9, body extent -1.1,-0.9 1.1,0.9, height 1.2
L0603_H0P8 [mm]
  rect 0.8x0.95 smd mask+0.05: 1(-0.8,0) 2(0.8,0)
  silkscreen extent -1.33,-0.6 1.33,0.6, body extent -0.87,-0.47 0.87,0.47, height 0.9
R0402 [mm]
  rect 0.51x0.7 smd mask+0.05: 1(-0.45,0) 2(0.45,0)
  silkscreen extent -0.72,-0.43 0.72,0.43, body extent -0.52,-0.3 0.52,0.3, height 0.4
SWI_JIUBABA_C-TS-02H-2-5-B-V-T_R_BLUE [mm] "BLUE"
  rect 0.75x1 smd mask+0.05: 1(-2.225,0.75) 2(2.225,0.75) 3(-2.225,-0.75) 4(2.225,-0.75)
  silkscreen extent -1.85,-1.6 1.85,1.6, body extent -2.45,-1.6 2.45,1.6, height 2.6

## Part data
B1: library part MCD-00172, "Switch HW SMD blue", Manufacturer=JIUBABA, Manufacturer_Part_Number="C-TS-02H-2.5-B-V-T/R BLUE"
C1 C4 C7 C8 C9 C10 C11 C12 C17 C19 C20 C21 C22 C23 C24 C25 C26 C27 C28 C78 C80 C82: library part MCD-00006, "Capacitor, MLCC, 100nF, 16V, X7R, 10%, 0402, T=0.5mm", Alternate_Manufacturer=MURATA, Alternate_Manufacturer_Part_Number=GCM155R71C104KA55D, Manufacturer=YAGEO, Manufacturer_Part_Number=CC0402KRX7R7BB104, Package=C0402
C2 C13 C14 C30 C32 C35 C36 C37 C41 C45 C46 C47 C48 C50 C53 C54: library part MCD-00095, "Capacitor, MLCC, 1uF, 6V3, X5R, 10%, 0402, T=0,5mm", Alternate_Manufacturer=MURATA, Alternate_Manufacturer_Part_Number=GRM155R60J105KE19, Manufacturer_Part_Number=GRM155R61E105KA12, Package=C0402
C3 C5 C6: library part MCD-01823, "Capacitor,MLCC,2.2uF,6V3,X5R,10%,0402,T=0.5", Manufacturer=MURATA, Manufacturer_Part_Number=GRM155R60J225KE95D, Package=C0402
C15 C16 C18 C31 C33 C39 C42: library part MCD-00099, "Capacitor, MLCC, 10uF, 10V, X5R, 10%, 0603, T=0,8mm", Manufacturer=MURATA, Manufacturer_Part_Number=GRM188R61A106KE69D, Package=C0603
C29 C34 C38 C40: library part MCD-00100, "Capacitor, MLCC, 22uF, 6V3, X5R, 20%, 0603, T=0,8mm", Manufacturer=MURATA, Manufacturer_Part_Number=GRM188R60J226MEA0J, Package=C0603
C43 C49 C51 C52: library part MCD-01356, "Capacitor, MLCC, 4.7uF, 6V3, X5R, 20%, 0402, T=0,5mm", Manufacturer=MURATA, Manufacturer_Part_Number=GRM155R60J475ME47, Package=C0402
C44: library part MCD-00011, "Capacitor, MLCC, 10nF, 16V, X7R, 10%, 0402, T=0.5mm", Manufacturer=YAGEO, Manufacturer_Part_Number=CC0402KRX7R7BB103, Package=C0402
C55 C56 C57: library part MCD-01462, "Capacitor, MLCC, 3.3nF, 16V, X7R, 10%, 0402, T=0.5mm", Manufacturer=YAGEO, Manufacturer_Part_Number=CC0402KRX7R7BB332, Package=C0402
C58 C59: library part MCD-00198, "Capacitor, MLCC, 1nF, 16V, X7R, 10%, 0402, T=0.5mm", Manufacturer=YAGEO, Manufacturer_Part_Number=CC0402KRX7R7BB102, Package=C0402
C79 C81 C83: library part MCD-00012, "Capacitor, MLCC, 2.2uF, 10V, X5R, 10%, 0603, T=0,8mm", Alternate_Manufacturer=KEMET, Alternate_Manufacturer_Part_Number=C0603C225K8PACTU, Manufacturer=YAGEO, Manufacturer_Part_Number=CC0603KRX5R6BB225, Package=C0603
L1 L2 L3 L4: library part MCD-01491, "Inductors 1.0uH 54mOhms3.3A +/-20% 2016", Manufacturer=MURATA, Manufacturer_Part_Number=DFE201612P-1R0M, Package=2016
L5: library part MCD-01134, "IND 4.7uH 20% 80mA 600mhom 0603", Manufacturer=MURATA, Manufacturer_Part_Number=LQM18FN4R7M00D, Package=0603
R1 R31: library part MCD-00120, "Resistor,240R,0402,1%,1/16W", Manufacturer=YAGEO, Manufacturer_Part_Number=RC0402FR-07240RL, Package=R0402
R2: library part MCD-00119, "Resistor,100R,0402,1%,1/16W", Manufacturer=YAGEO, Manufacturer_Part_Number=RC0402FR-07100RL, Package=R0402
R3 R4 R5 R6 R7 R8 R9 R10 R11 R12 R13 R15 R16 R17 R18 R19 R20 R21 R22 R23 R24 R25 R26 R27 R34: library part MCD-00455, "Resistor,33R,0402,1%,1/16W", Manufacturer=YAGEO, Manufacturer_Part_Number=RC0402FR-0733RL, Package=R0402
R14 R32 R40: library part MCD-00053, "Resistor,10K,0402,1%,1/16W", Manufacturer=YAGEO, Manufacturer_Part_Number=RC0402FR-0710KL, Package=R0402
R28 R29 R30 R33 R35 R36: library part MCD-00061, "Resistor,1K,0402,1%,1/16W", Manufacturer=YAGEO, Manufacturer_Part_Number=RC0402FR-071KL, Package=R0402
R37 R38: library part MCD-00068, "Resistor,1K5,0402,1%,1/16W", Manufacturer=YAGEO, Manufacturer_Part_Number=RC0402FR-071K5L, Package=R0402
R39 R41 R42: library part MCD-00052, "Resistor,0R,0402,5%,1/16W", Manufacturer=YAGEO, Manufacturer_Part_Number=RC0402JR-070RL, Package=R0402
R43: library part MCD-00063, "Resistor,47K,0402,1%,1/16W", Manufacturer=YAGEO, Manufacturer_Part_Number=RC0402FR-0747KL, Package=R0402
U1: library part MCD-01144, "MPU TFBGA10x10 secure boot+crypto", Manufacturer=STMICROELECTRONICS, Manufacturer_Part_Number=STM32MP157CAD3
U2: library part MCD-01811, "Memory,DDR3L,4Gb,256Mbx16,933Mhz,1V35,TFBGA", Manufacturer=NANYA
U4: library part MCD-01650, "ST PMIC:  4 step-down + 1 advanced boost SMPS, 6 LDOs, 2 pwr switches, DDR Vref, NVM option 'A' for IO@3.3V", Manufacturer=STMICROELECTRONICS, Manufacturer_Part_Number=STPMIC1APQR, Package="WFQFN 5.0x6.0x0.80mm"
U5: library part MCD-00110, "Memory,e-MMC,4GB,3V3,WFBGA,153pins", Manufacturer=TOSHIBA, Manufacturer_Part_Number=THGBMDG5D1LBAIL

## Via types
v1: diameter 0.4, hole 0.2, Top Layer to Bottom Layer, tented both sides, 260 vias
v2: diameter 0.6, hole 0.3, Top Layer to Bottom Layer, tented both sides, 74 vias
v3: diameter 0.4, hole 0.2, Top Layer to Signal Layer 1, tented top, 2 vias

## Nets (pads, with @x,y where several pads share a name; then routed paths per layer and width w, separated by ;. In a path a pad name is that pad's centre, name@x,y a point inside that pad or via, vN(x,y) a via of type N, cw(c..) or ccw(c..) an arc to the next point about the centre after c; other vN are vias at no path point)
3V3: C32.2 C40.2 C78.2 C79.2 L4.2 U4.22 U4.27 U5.E6 U5.F5 U5.J10 U5.K9 | length 48
  Top Layer w0.175: U5.J10@27.15,88.475 U5.K9@27.65,88.975 v1(27.65,89.45) ; U5.E6@29.15,86.475 U5.F5@29.65,86.975 v1(30.075,86.975)
  Top Layer w0.2: 10.825,82.4 11.175,82.75 U4.22@11.375,82.75 ; v1(13.525,80.8) 13.525,81.4 13.725,81.6 U4.27@13.725,82.1
  Top Layer w0.3: C32.2@8.425,80.05 v1(8.425,80.4) 8.425,81 8.825,81.4 9.825,81.4 10.825,82.4
  Top Layer w0.5: C40.2@11.45,77.1 v1(12.125,77.1)
  Top Layer w0.6: C40.2@11.45,77.1 L4.2@11.45,78.3
  Signal Layer 2 w0.3: v1(8.425,80.4) 9.788,79.038 11.725,77.1 v1(12.125,77.1)
  Bottom Layer w0.1: C79.2@26.8,89.575 C79.2@26.925,89.45 ; v1@30,87.05 v1(30.075,86.975)
  Bottom Layer w0.3: v1(13.525,80.8) 12.85,80.125 12.85,77.3 12.65,77.1 v1(12.125,77.1) 12.125,81.4 12.65,81.925 19.761,81.925 21.686,83.85 22.186,83.85 22.45,84.114 22.45,84.486 22.331,84.606 23.006,84.606 23.625,85.225 23.625,86.4 C79.2@26.8,89.575 ; C79.2@26.925,89.45 v1(27.65,89.45) 28.1,89.45 C78.2@30,87.55 v1@30,87.05
5V_VIN: C18.2 C31.2 C33.2 C39.2 C41.2 C51.1 R43.2 U4.8 U4.12 U4.19 U4.24 U4.28 U4.36 U4.37 | length 16.6
  Top Layer w0.09: v1(14.125,80.7) U4.28@14.125,82.1 ; R43.2@19.775,81.725 R43.2@19.9,81.6
  Top Layer w0.1: R43.2@19.775,81.725 C51.1@19.775,82.4
  Top Layer w0.2: C39.2@10.625,80 10.85,80.225 10.85,80.425 11.425,81 11.925,81 12.525,81.6 U4.24@12.525,82.1 ; 10.675,83.95 U4.19@11.375,83.95 ; v1(10.825,87.4) 11.225,87.4 11.625,87 U4.12@12.125,87 ; C31.2@13.725,80 13.75,80.025 14.125,80.4 v1(14.125,80.7) ; U4.8@13.725,87 13.725,88.4 v1(13.525,88.6) 13.525,89.1 C33.2@13.725,89.3 ; U4.36@17.275,83.15 17.674,83.15 18.099,82.725 18.35,82.725 18.675,82.4 v1(19.125,82.4) C51.1@19.775,82.4 C51.1@19.8,82.4 ; U4.37@17.275,83.55 17.9,83.55 v1(18.125,83.325)
  Top Layer w0.3: C41.2@8.975,83.5 v1(9.525,83.5) 9.975,83.95 10.675,83.95
  other v1: 10.425,80.6
A0: R3.2 U2.N3 | length 33
  Top Layer w0.12: U2.N3@50.65,67.825 v1(51.05,68.225)
  Bottom Layer w0.12: R3.2@39.55,72.9 R3.2@39.55,72.925 40.825,72.925 40.975,73.075 40.975,74.175 40.855,74.295 38.145,74.295 38.065,74.375 38.065,74.65 38.14,74.725 40.85,74.725 40.955,74.83 40.955,75.03 41.122,75.197 41.122,75.359 40.955,75.526 40.955,76.495 40.795,76.655 40.501,76.655 40.16,76.996 40.16,77.604 40.428,77.872 ; 40.425,77.875 40.495,77.945 42.73,77.945 42.8,77.875 ; 42.797,77.872 42.969,77.7 43.125,77.7 43.37,77.945 44.587,77.945 45.5,77.032 45.5,69.275 46.9,67.875 46.99,67.785 50.685,67.785 51.05,68.15 v1(51.05,68.225)
A1: R4.2 U2.P7 | length 35.1
  Top Layer w0.12: U2.P7@49.85,64.625 v1(50.25,64.225)
  Bottom Layer w0.12: 38.7,62.195 37.945,62.195 37.485,61.735 37.485,59.859 38.139,59.205 39.421,59.205 39.801,58.825 40.27,58.825 40.65,59.205 40.876,59.205 41.251,58.83 41.744,58.83 42.119,59.205 42.401,59.205 42.851,58.755 43.755,58.755 43.85,58.85 43.85,59.35 43.925,59.425 44.225,59.425 44.305,59.345 44.305,58.82 44.37,58.755 46.426,58.755 46.831,58.35 47.469,58.35 47.569,58.45 47.9,58.45 48,58.35 49.806,58.35 49.925,58.469 49.925,58.675 49.82,58.78 48.229,58.78 46.19,60.819 46.19,62.959 46.575,63.344 46.575,63.6 46.765,63.79 47.649,63.79 48.45,64.591 49.884,64.591 49.95,64.525 v1(50.25,64.225) ; 38.7,62.2 38.825,62.325 38.825,62.5 38.975,62.65 39.2,62.65 39.325,62.525 39.325,62.375 39.5,62.2 39.5,62.195 39.67,62.195 39.8,62.325 39.8,64.281 39.691,64.39 39.685,64.39 R4.2@39.4,64.675
A2: R5.2 U2.P3 | length 33
  Top Layer w0.12: U2.P3@49.85,67.825 v1(50.25,68.225)
  Bottom Layer w0.12: R5.2@38.525,72.9 R5.2@38.525,72.95 38.525,73.325 38.625,73.425 40.43,73.425 40.555,73.55 40.555,73.77 40.45,73.875 38.425,73.875 38.275,73.725 37.85,73.725 37.725,73.85 37.645,73.93 37.645,75.065 37.725,75.145 40.32,75.145 40.455,75.28 40.455,76.095 39.74,76.81 39.74,77.784 40.326,78.37 44.756,78.37 45.935,77.191 45.935,69.449 ; 45.925,69.45 47.3,68.075 49.829,68.075 49.954,68.2 50.25,68.2 50.275,68.2 v1(50.25,68.225) v1@50.2,68.275
A3: R6.2 U2.N2 | length 34
  Top Layer w0.12: U2.N2@50.65,68.625 v1(51.05,69.025)
  Bottom Layer w0.12: R6.2@37.5,72.35 37.5,73.481 37.225,73.756 37.225,75.25 37.54,75.565 39.9,75.565 40.035,75.7 40.035,75.921 39.111,76.845 37.48,76.845 37.375,76.95 37.375,77.175 37.5,77.3 39.225,77.3 39.315,77.39 39.315,77.725 39.32,77.73 39.32,77.958 40.212,78.85 44.87,78.85 46.355,77.365 46.355,69.623 47.598,68.38 ; 47.575,68.4 47.6,68.375 49.181,68.375 49.719,68.375 49.969,68.625 50.65,68.625 v1(51.05,69.025)
A4: R7.2 U2.P8 | length 37.8
  Top Layer w0.12: v1(49.45,62.35) 49.45,63.425 U2.P8@49.85,63.825
  Bottom Layer w0.12: R7.2@33.85,63.425 33.85,62.75 34.155,62.445 34.155,60.376 34.53,60.001 34.53,58.656 37.811,55.375 38.85,55.375 ; 38.85,55.38 51.544,55.38 53.32,57.156 53.32,58.725 53.635,59.04 53.635,59.749 53.265,60.119 52.919,60.119 52.807,60.232 52.807,60.482 52.875,60.55 53.55,60.55 53.65,60.65 53.65,60.85 53.575,60.925 52.114,60.925 51.744,61.295 51.463,61.295 51.304,61.454 51.304,62.021 51.01,62.315 49.533,62.315 v1@49.474,62.374
A5: R8.2 U2.P2 | length 37.5
  Top Layer w0.12: U2.P2@49.85,68.625 v1(50.25,69.025)
  Bottom Layer w0.12: R8.2@35.05,69.825 35.05,70.225 34.85,70.425 34.85,72.025 35.125,72.3 35.35,72.3 35.75,72.7 35.75,73.042 35.954,73.246 35.954,75.76 36.225,76.032 36.225,76.293 36.115,76.403 36.115,77.697 36.83,78.412 36.83,79.149 37.201,79.52 37.687,79.52 38.277,80.11 45.392,80.11 46.376,79.126 46.576,79.126 46.7,79.25 46.7,79.45 46.287,79.862 46.287,79.988 46.4,80.1 46.675,80.1 47.3,79.475 47.3,79.2 46.913,78.812 46.913,78.589 47.615,77.887 47.615,77.004 48.145,76.474 48.145,72.98 48.687,72.438 ; 48.691,72.441 48.795,72.336 48.795,71.705 49.55,70.95 49.55,70.175 49.45,70.075 49.45,69.811 49.05,69.411 49.05,68.8 49.175,68.675 49.291,68.675 49.301,68.665 49.599,68.665 49.959,69.025 v1(50.25,69.025)
A6: R9.2 U2.R8 | length 37.7
  Top Layer w0.12: v1(48.65,62.35) 48.65,63.425 U2.R8@49.05,63.825
  Bottom Layer w0.12: R9.2@35.075,67.1 35.075,67 34.65,66.575 34.65,64.85 34.575,64.775 34.575,60.55 34.95,60.175 34.95,58.83 37.235,56.545 37.971,55.81 51.38,55.81 52.9,57.33 52.9,59.545 51.57,60.875 51.289,60.875 50.814,61.35 49.925,61.35 48.925,62.35 v1(48.65,62.35)
A7: R10.2 U2.R2 | length 37.5
  Top Layer w0.12: U2.R2@49.05,68.625 v1(49.45,69.025) v1@49.45,69.05
  Bottom Layer w0.12: R10.2@34.3,71.65 34.3,72.434 35.534,73.668 35.534,76.264 35.695,76.425 35.695,77.871 36.41,78.586 36.41,79.323 37.027,79.94 37.513,79.94 38.103,80.53 46.839,80.53 47.72,79.649 47.72,78.376 48.035,78.061 48.035,77.178 48.565,76.648 48.565,73.16 48.7,73.025 48.875,73.025 49,73.15 49,74.7 49.1,74.8 49.35,74.8 49.45,74.7 49.45,71.825 50.225,71.05 50.225,69.791 49.734,69.3 49.725,69.3 ; v1(49.45,69.025) 49.99,69.565
A8: R11.2 U2.T8 | length 33.4
  Top Layer w0.12: v1(47.875,62.35) 47.89,62.365 47.89,63.465 U2.T8@48.25,63.825
  Bottom Layer w0.12: 36.175,62.8 36.2,62.825 ; R11.2@36.2,64 R11.2@36.2,63.8 36.2,62.826 ; 37.45,57.519 35.805,59.163 35.805,62.431 36.2,62.826 ; 37.45,57.519 38.044,56.925 39.325,56.925 39.55,56.7 40.025,56.7 40.4,57.075 40.625,57.075 41,56.7 41.25,56.7 41.625,57.075 41.8,57.075 42.175,56.7 42.375,56.7 42.75,57.075 43.125,57.075 43.5,56.7 43.825,56.7 44.2,57.075 44.475,57.075 44.85,56.7 45.1,56.7 45.475,57.075 45.73,57.075 46.155,56.65 51.032,56.65 52.06,57.678 52.06,59.197 51.222,60.035 50.941,60.035 50.516,60.46 49.565,60.46 49.12,60.905 48.737,60.905 48.508,61.133 48.302,61.133 47.875,61.561 v1(47.875,62.35)
A9: R12.2 U2.R3 | length 33.2
  Top Layer w0.12: v1(48.65,69.025) 48.65,68.225 U2.R3@49.05,67.825
  Bottom Layer w0.12: R12.2@35.4,71.7 35.525,71.7 36.178,72.353 36.178,72.522 36.66,73.004 36.66,73.133 36.374,73.42 36.374,75.586 36.756,75.969 36.756,76.356 36.535,76.577 36.535,77.523 37.164,78.152 38.326,78.152 38.4,78.226 38.4,78.5 38.25,78.65 37.325,78.65 37.25,78.725 37.25,78.975 37.375,79.1 37.861,79.1 38.451,79.69 45.218,79.69 47.195,77.713 47.195,72.742 47.825,72.112 47.825,71.881 47.305,71.361 47.305,69.861 47.846,69.32 48.355,69.32 v1(48.65,69.025)
A10: R13.2 U2.L7 | length 36
  Top Layer w0.1: U2.L7@52.25,64.625 v1(52.65,64.225)
  Bottom Layer w0.12: R13.2@38.25,64 38.25,63.95 38.057,63.757 38.057,63.495 36.645,62.083 36.645,59.511 37.797,58.359 39.08,58.359 39.523,57.915 46.078,57.915 46.493,57.5 50.694,57.5 51.22,58.026 51.22,58.849 50.874,59.195 50.593,59.195 50.168,59.62 48.577,59.62 47.03,61.167 47.03,62.608 47.497,63.075 47.925,63.075 48.375,63.525 52.1,63.525 52.35,63.275 52.7,63.275 52.875,63.45 52.875,64 v1(52.65,64.225)
A11: R15.2 U2.R7 | length 33.7
  Top Layer w0.12: v1(47.5,64.15) 47.525,64.125 47.956,64.125 48.076,64.245 48.705,64.245 U2.R7@49.05,64.59
  Bottom Layer w0.12: 39.025,59.625 39.595,59.625 39.975,59.245 40.096,59.245 40.476,59.625 41.05,59.625 41.425,59.25 41.57,59.25 41.945,59.625 42.575,59.625 43.025,59.175 43.325,59.175 43.4,59.25 43.4,59.425 43.15,59.675 43.15,59.8 43.285,59.935 43.448,59.935 43.713,60.2 43.962,60.2 44.263,59.899 44.701,59.899 44.816,59.784 ; 39.025,59.63 38.308,59.63 37.905,60.033 37.905,60.549 38.125,60.769 38.125,60.875 37.925,61.075 37.925,61.525 38.175,61.775 38.45,61.775 38.575,61.65 38.575,61.025 38.705,60.895 40.75,60.895 40.85,60.995 40.85,61.132 40.657,61.325 39.1,61.325 39.025,61.4 39.025,61.675 39.125,61.775 40.25,61.775 40.4,61.925 40.4,62.52 40.22,62.7 40.22,63.37 40.4,63.55 R15.2@40.4,64.25 ; 44.816,59.791 44.816,59.784 ; v1(47.5,64.15) 47.475,64.175 46.27,64.175 46.12,64.025 46.12,63.495 45.77,63.145 45.77,60.645 47.4,59.015 47.4,58.875 47.295,58.77 47.005,58.77 46.475,59.3 46.224,59.3 46.099,59.175 44.85,59.175 44.725,59.3 44.725,59.459 44.875,59.609 44.875,59.725 44.816,59.784
A12: R16.2 U2.N7 | length 33.3
  Top Layer w0.12: U2.N7@50.65,64.625 v1(51.05,64.225)
  Bottom Layer w0.12: R16.2@39.275,63.075 38.45,63.075 38.35,62.975 38.35,62.75 38.234,62.634 37.791,62.634 37.065,61.909 37.065,59.685 37.971,58.779 39.254,58.779 39.682,58.35 40.389,58.35 40.714,58.675 40.812,58.675 41.137,58.35 41.858,58.35 42.183,58.675 42.337,58.675 42.677,58.335 46.252,58.335 46.662,57.925 50.525,57.925 50.8,58.2 50.8,58.675 50.7,58.775 50.419,58.775 49.994,59.2 48.403,59.2 46.61,60.993 46.61,62.785 47.25,63.425 47.775,63.425 48.375,64.025 49.7,64.025 49.86,63.865 50.665,63.865 51.025,64.225 v1(51.05,64.225)
A13: R17.2 U2.T3 | length 33.6
  Top Layer w0.12: v1(47.725,68.9) 47.725,68.35 U2.T3@48.25,67.825
  Bottom Layer w0.12: R17.2@36.475,71.775 36.598,71.898 36.598,72.348 37.08,72.83 37.08,73.307 36.794,73.594 36.794,75.413 37.366,75.985 38.935,75.985 39.025,76.075 39.025,76.337 38.937,76.425 37.306,76.425 36.955,76.776 36.955,77.349 37.338,77.732 38.707,77.732 38.875,77.9 38.875,78.125 39.309,78.559 39.309,78.741 39.2,78.85 38.675,78.85 38.525,79 38.525,79.17 38.625,79.27 45.044,79.27 46.775,77.539 46.775,72.568 47.225,72.118 47.225,71.875 46.775,71.425 46.775,69.797 47.672,68.9 v1(47.725,68.9)
A14: R18.2 U2.T7 | length 31.3
  Top Layer w0.12: v1(47.75,64.625) U2.T7@48.25,64.625
  Bottom Layer w0.12: R18.2@40.85,65.85 40.925,65.775 40.925,63.46 40.64,63.175 40.64,62.874 40.925,62.589 40.925,61.651 41.656,60.92 42.235,60.92 42.33,60.825 42.33,60.555 42.25,60.475 38.425,60.475 38.325,60.375 38.325,60.207 38.482,60.05 39.764,60.05 39.907,59.907 40.164,59.907 40.307,60.05 41.1,60.05 ; 41.1,60.045 41.224,60.045 41.384,59.884 41.611,59.884 41.776,60.05 42.75,60.05 42.825,60.125 42.825,60.25 42.93,60.355 43.274,60.355 43.65,60.731 43.65,62.58 43.75,62.68 44.025,62.68 44.08,62.625 44.08,60.676 44.426,60.33 44.725,60.33 ; 44.725,60.325 44.875,60.325 45.295,59.905 45.295,59.7 45.4,59.595 45.925,59.595 46,59.67 46,59.821 45.35,60.471 45.35,63.319 45.7,63.669 45.7,64.425 45.875,64.6 v1@47.75,64.6
A15: R34.2 U2.M7 | length 33.8
  Top Layer w0.09: v1(39.65,67.075) 40,67.075 40.1,67.175 R34.2@40.1,67.675
  Top Layer w0.1: U2.M7@51.45,64.625 v1(51.85,64.225)
  Bottom Layer w0.12: v1(39.65,67.075) 39.85,67.275 41.175,67.275 41.35,67.1 41.35,61.82 41.83,61.34 42.61,61.34 42.75,61.2 42.75,60.875 42.85,60.775 43.1,60.775 43.23,60.905 43.23,62.445 43.075,62.6 43.075,65.65 43.175,65.75 43.32,65.75 43.525,65.545 43.525,63.2 43.625,63.1 44.4,63.1 44.5,63 44.5,60.85 44.6,60.75 44.825,60.75 44.93,60.855 44.93,63.493 45.25,63.813 45.25,64.75 45.365,64.865 45.54,64.865 45.685,65.01 50.215,65.01 50.575,64.65 51.425,64.65 v1(51.85,64.225)
BA0: R19.2 U2.M2 | length 33
  Top Layer w0.12: U2.M2@51.45,68.625 v1(51.85,69.025)
  Bottom Layer w0.12: R19.2@41.35,72.325 41.395,72.37 41.395,73.033 41.75,73.388 41.75,73.557 41.405,73.902 41.405,74.768 42.052,75.415 42.815,75.415 42.885,75.485 42.885,75.765 42.775,75.875 42.6,75.875 42.28,76.195 42.28,77.045 42.175,77.15 41.975,77.15 41.825,77 41.825,75.825 41.625,75.625 41.45,75.625 41.375,75.7 41.375,76.975 41.275,77.075 40.703,77.075 40.58,77.198 40.58,77.43 40.665,77.515 42.56,77.515 42.905,77.17 43.201,77.17 43.546,77.515 44.423,77.515 45.08,76.858 45.08,69.095 46.69,67.485 47.703,67.485 47.713,67.495 50.949,67.495 51.44,67.986 51.44,68.376 51.85,68.786 v1(51.85,69.025)
BA1: R20.2 U2.N8 | length 35.9
  Top Layer w0.12: v1@50.225,62.675 50.237,62.687 50.25,62.7 50.25,63.425 U2.N8@50.65,63.825
  Bottom Layer w0.12: R20.2@35.175,64 R20.2@35.2,64 ; R20.2@35.175,64.025 35.187,64.013 R20.2@35.2,64 ; v1@50.225,62.675 49.634,62.675 49.584,62.725 48.5,62.725 48.29,62.515 48.29,62.201 48.65,61.841 48.65,61.586 48.911,61.325 49.294,61.325 49.739,60.88 50.69,60.88 51.115,60.455 51.396,60.455 52.48,59.371 52.48,57.504 51.206,56.23 45.981,56.23 45.961,56.25 45.708,56.503 45.497,56.503 45.244,56.25 44.706,56.25 44.406,56.55 44.269,56.55 43.969,56.25 43.356,56.25 43.056,56.55 42.819,56.55 42.519,56.25 38.125,56.25 37.276,57.099 35.385,58.989 35.385,62.605 35.56,62.78 35.56,63.69 35.25,64 R20.2@35.2,64
  other v1: 50.25,62.675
